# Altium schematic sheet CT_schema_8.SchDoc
size 147 x 119 mm
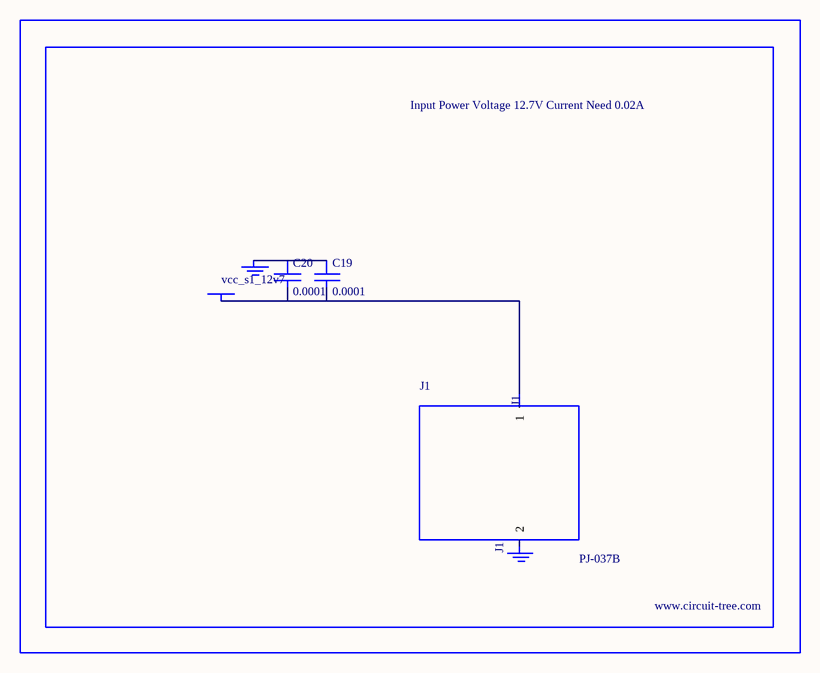
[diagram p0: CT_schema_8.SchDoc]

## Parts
BORDER7  (no value)
C19  0.0001  [EXV-9H]
C20  0.0001  [EXV-9H]
GND_INSTANCE_7_0  (no value)
GND_INSTANCE_7_1  (no value)
J1  PJ-037B  [PJ-037B_PACKAGE]
POWER_INSTANCE_7_0  vcc_s1_12v7

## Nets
NetC19_1: C19.1 C20.1 GND_INSTANCE_7_0.0(GND)
NetC19_2: C19.2 C20.2 J1.1 POWER_INSTANCE_7_0.0(PWR)

Not connected (* = marked no-connect by the designer): GND_INSTANCE_7_1 0(GND); J1 2

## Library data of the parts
BORDER7 = BORDER_PAGE7
C19 C20 = EDK107M035A9HAA
GND_INSTANCE_7_0 GND_INSTANCE_7_1 = GND
POWER_INSTANCE_7_0 = PWR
